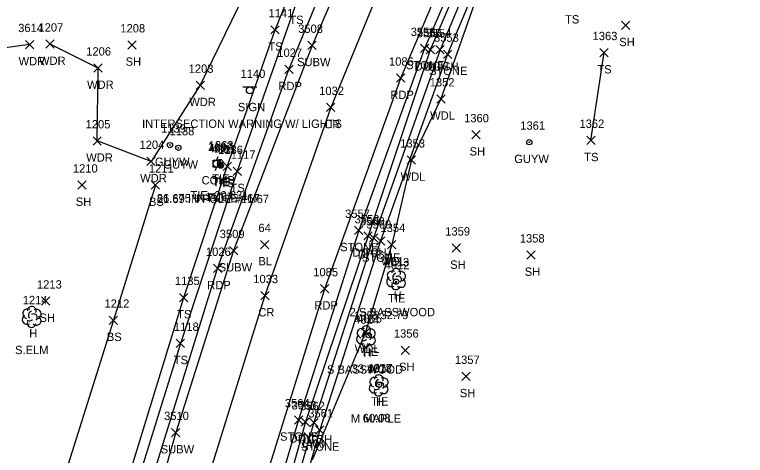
# Model space of a CAD drawing. Extents: x 1634209 to 1639641, y 608564 to 612258.
# Drawn here: x 1639356.8 to 1639532.2, y 611847.1 to 611953 of the extents above; entities that cross this region are included whole.
import ezdxf

# ---------------------------------------------------------------- set-up
doc = ezdxf.new("R2010")
doc.units = 0
for name, color, linetype in [('C_A', 7, 'Continuous'), ('C_C', 7, 'Continuous'), ('C_I', 7, 'Continuous'), ('C_TIC', 7, 'Continuous'), ('CBP', 7, 'Continuous'), ('D_A', 7, 'Continuous'), ('D_I', 7, 'Continuous'), ('D_TIC', 7, 'Continuous'), ('DD', 7, 'Continuous'), ('L_A', 7, 'Continuous'), ('L_C', 7, 'Continuous'), ('L_I', 7, 'Continuous'), ('L_TIC', 7, 'Continuous'), ('LASF', 7, 'Continuous'), ('LAWA', 7, 'Continuous'), ('LELB', 7, 'Continuous'), ('LTD', 7, 'Continuous'), ('P_A', 7, 'Continuous'), ('P_I', 7, 'Continuous'), ('P_TIC', 7, 'Continuous'), ('PET', 7, 'Continuous'), ('PRC', 7, 'Continuous'), ('S_A', 7, 'Continuous'), ('S_C', 7, 'Continuous'), ('S_I', 7, 'Continuous'), ('SSGN', 7, 'Continuous'), ('U_A', 7, 'Continuous'), ('U_C', 7, 'Continuous'), ('U_I', 7, 'Continuous'), ('U_TIC', 7, 'Continuous'), ('UP', 7, 'Continuous'), ('UPGW', 7, 'Continuous'), ('UW', 7, 'Continuous')]:
    doc.layers.add(name, color=color, linetype=linetype)

msp = doc.modelspace()

# ---------------------------------------------------------------- linework, layer by layer
at = {"layer": 'C_TIC'}
for points in [[(1639415.86, 611896.74), (1639417.85, 611898.74)], [(1639417.85, 611896.74), (1639415.86, 611898.74)]]:
    msp.add_lwpolyline(points, dxfattribs=at)
at = {"layer": 'CBP'}
for centre, radius in [((1639406.14, 611917.58), 0.625), ((1639406.14, 611917.58), 0.0833), ((1639406.16, 611916.87), 0.625), ((1639406.3, 611916.69), 0.625), ((1639406.16, 611916.87), 0.0833), ((1639406.3, 611916.69), 0.0833), ((1639448.41, 611888.82), 0.625), ((1639448.41, 611888.82), 0.0833), ((1639441.81, 611875.95), 0.625), ((1639441.81, 611875.95), 0.0833), ((1639444.33, 611864.06), 0.625), ((1639444.33, 611864.06), 0.0833)]:
    msp.add_circle(centre, radius, dxfattribs=at)
at = {"layer": 'D_TIC'}
for points in [[(1639455.59, 611943.52), (1639457.59, 611945.52)], [(1639457.59, 611943.52), (1639455.59, 611945.52)], [(1639457.96, 611943.55), (1639459.96, 611945.55)], [(1639459.96, 611943.55), (1639457.96, 611945.55)], [(1639440.68, 611898.83), (1639442.68, 611900.83)], [(1639442.68, 611898.83), (1639440.68, 611900.83)], [(1639441.97, 611898.33), (1639443.97, 611900.33)], [(1639443.97, 611898.33), (1639441.97, 611900.33)], [(1639425.6, 611854.12), (1639427.6, 611856.12)], [(1639427.6, 611854.12), (1639425.6, 611856.12)], [(1639427.64, 611853.96), (1639429.64, 611855.96)], [(1639429.64, 611853.96), (1639427.64, 611855.96)]]:
    msp.add_lwpolyline(points, dxfattribs=at)
at = {"layer": 'DD'}
for points in [[(1639560.57, 612129.01), (1639556.53, 612119.06), (1639548.81, 612104.26), (1639529.12, 612083.62), (1639507.53, 612047.31), (1639491.18, 612019.02), (1639473.22, 611983.07), (1639456.59, 611944.52), (1639441.68, 611899.83), (1639426.6, 611855.12), (1639414, 611809.64), (1639403.11, 611769.87), (1639390.43, 611727.49), (1639379.87, 611693.81), (1639369.1, 611662.09), (1639367.84, 611659.83)], [(1639561.94, 612128.14), (1639558.11, 612117.59), (1639549.56, 612103.15), (1639530.32, 612082.73), (1639508.94, 612046.64), (1639492.68, 612018.5), (1639474.74, 611982.05), (1639458.96, 611944.55), (1639442.97, 611899.33), (1639428.64, 611854.96), (1639415.08, 611808.28), (1639405.32, 611769.46), (1639392.22, 611726.77), (1639382.52, 611693.71), (1639371.49, 611661), (1639370.19, 611658.57)]]:
    msp.add_lwpolyline(points, dxfattribs=at)
at = {"layer": 'L_TIC'}
for points in [[(1639502.48, 611949.4), (1639504.48, 611951.4)], [(1639504.48, 611949.4), (1639502.48, 611951.4)], [(1639418.32, 611948.32), (1639420.32, 611950.32)], [(1639420.32, 611948.32), (1639418.32, 611950.32)], [(1639359.4, 611944.78), (1639361.4, 611946.78)], [(1639361.4, 611944.78), (1639359.4, 611946.78)], [(1639364.3, 611944.9), (1639366.3, 611946.9)], [(1639366.3, 611944.9), (1639364.3, 611946.9)], [(1639383.96, 611944.69), (1639385.96, 611946.69)], [(1639385.96, 611944.69), (1639383.96, 611946.69)], [(1639454.22, 611943.85), (1639456.22, 611945.85)], [(1639456.22, 611943.85), (1639454.22, 611945.85)], [(1639459.76, 611942.45), (1639461.76, 611944.45)], [(1639461.76, 611942.45), (1639459.76, 611944.45)], [(1639497.31, 611942.84), (1639499.31, 611944.84)], [(1639499.31, 611942.84), (1639497.31, 611944.84)], [(1639375.82, 611939.14), (1639377.82, 611941.14)], [(1639377.82, 611939.14), (1639375.82, 611941.14)], [(1639400.36, 611935), (1639402.36, 611937)], [(1639402.36, 611935), (1639400.36, 611937)], [(1639458.16, 611931.72), (1639460.16, 611933.72)], [(1639460.16, 611931.72), (1639458.16, 611933.72)], [(1639466.55, 611923.11), (1639468.55, 611925.11)], [(1639468.55, 611923.11), (1639466.55, 611925.11)], [(1639375.62, 611921.64), (1639377.62, 611923.64)], [(1639377.62, 611921.64), (1639375.62, 611923.64)], [(1639494.15, 611921.77), (1639496.15, 611923.77)], [(1639496.15, 611921.77), (1639494.15, 611923.77)], [(1639388.58, 611916.71), (1639390.58, 611918.71)], [(1639390.58, 611916.71), (1639388.58, 611918.71)], [(1639451.06, 611917.05), (1639453.06, 611919.05)], [(1639453.06, 611917.05), (1639451.06, 611919.05)], [(1639406.84, 611915.5), (1639408.84, 611917.5)], [(1639408.84, 611915.5), (1639406.84, 611917.5)], [(1639409.24, 611914.34), (1639411.24, 611916.34)], [(1639411.24, 611914.34), (1639409.24, 611916.34)], [(1639372, 611911.03), (1639374, 611913.03)], [(1639374, 611911.03), (1639372, 611913.03)], [(1639389.61, 611911.03), (1639391.61, 611913.03)], [(1639391.61, 611911.03), (1639389.61, 611913.03)], [(1639438.42, 611900.14), (1639440.42, 611902.14)], [(1639440.42, 611900.14), (1639438.42, 611902.14)], [(1639443.67, 611897.59), (1639445.67, 611899.59)], [(1639445.67, 611897.59), (1639443.67, 611899.59)], [(1639446.34, 611896.74), (1639448.34, 611898.74)], [(1639448.34, 611896.74), (1639446.34, 611898.74)], [(1639461.89, 611895.9), (1639463.89, 611897.9)], [(1639463.89, 611895.9), (1639461.89, 611897.9)], [(1639479.79, 611894.22), (1639481.79, 611896.22)], [(1639481.79, 611894.22), (1639479.79, 611896.22)], [(1639363.29, 611883.16), (1639365.29, 611885.16)], [(1639365.29, 611883.16), (1639363.29, 611885.16)], [(1639396.42, 611884.01), (1639398.42, 611886.01)], [(1639398.42, 611884.01), (1639396.42, 611886.01)], [(1639379.51, 611878.56), (1639381.51, 611880.56)], [(1639381.51, 611878.56), (1639379.51, 611880.56)], [(1639440.05, 611875.68), (1639442.05, 611877.68)], [(1639442.05, 611875.68), (1639440.05, 611877.68)], [(1639395.62, 611873), (1639397.62, 611875)], [(1639397.62, 611873), (1639395.62, 611875)], [(1639449.62, 611871.36), (1639451.62, 611873.36)], [(1639451.62, 611871.36), (1639449.62, 611873.36)], [(1639464.2, 611865.06), (1639466.2, 611867.06)], [(1639466.2, 611865.06), (1639464.2, 611867.06)], [(1639423.97, 611854.61), (1639425.97, 611856.61)], [(1639425.97, 611854.61), (1639423.97, 611856.61)], [(1639429.04, 611852.19), (1639431.04, 611854.19)], [(1639431.04, 611852.19), (1639429.04, 611854.19)]]:
    msp.add_lwpolyline(points, dxfattribs=at)
at = {"layer": 'LASF'}
for points in [[(1639558.56, 612130.45), (1639552.86, 612120.18), (1639541.01, 612102.18), (1639527.49, 612085.59), (1639505.85, 612048.28), (1639489.98, 612019.2), (1639472.04, 611983.89), (1639455.22, 611944.85), (1639439.42, 611901.14), (1639424.97, 611855.61), (1639411.65, 611810.44), (1639400.31, 611769.99), (1639387.4, 611727.33), (1639377.22, 611693.8), (1639367.21, 611662.75), (1639359.89, 611644.2)], [(1639564.17, 612127.3), (1639559.55, 612115.01), (1639546.48, 612097.15), (1639532.98, 612081.91), (1639511.96, 612045.66), (1639494.66, 612017.18), (1639476.15, 611980.34), (1639460.76, 611943.45), (1639444.67, 611898.59), (1639430.04, 611853.19), (1639417.13, 611807.26), (1639407.25, 611767.41), (1639395.02, 611725.74), (1639384.78, 611692.04), (1639373.34, 611660.29), (1639366.81, 611640.98)]]:
    msp.add_lwpolyline(points, dxfattribs=at)
at = {"layer": 'LAWA'}
for points in [[(1639621.29, 612162.67), (1639586.37, 612122.18), (1639574.47, 612128.38), (1639569.45, 612130.12), (1639568.95, 612119.64), (1639554.1, 612098.18), (1639539.81, 612087.62), (1639526.58, 612068.13), (1639518.72, 612053.78), (1639510.6, 612040.7), (1639492.01, 612011.11), (1639478.47, 611981.43), (1639467.99, 611958.08), (1639459.16, 611932.72), (1639452.06, 611918.05), (1639447.34, 611897.74), (1639441.05, 611876.68), (1639428.25, 611845.92)], [(1639373.01, 611979.94), (1639388.01, 611971.55), (1639400.87, 611973.02), (1639414.55, 611978.24), (1639413.38, 611960.74), (1639401.36, 611936), (1639389.58, 611917.71), (1639376.62, 611922.64), (1639376.82, 611940.14), (1639365.3, 611945.9)], [(1639360.4, 611945.78), (1639337.86, 611942.69), (1639328.3, 611925.99), (1639325.8, 611899.79), (1639322.13, 611876.77), (1639319.6, 611839.54), (1639313.3, 611808.51), (1639315.96, 611791.14), (1639292.51, 611779.22), (1639297.13, 611749.76), (1639287.19, 611716.77), (1639276.76, 611694.78), (1639243.82, 611692.54), (1639224.95, 611705.38), (1639202.4, 611705.49), (1639183.07, 611705.82), (1639163.18, 611694.66), (1639148.22, 611679.88), (1639133.72, 611654.57), (1639109.62, 611601.39), (1639094.77, 611617.67)]]:
    msp.add_lwpolyline(points, dxfattribs=at)
at = {"layer": 'LELB'}
for points in [[(1639563.38, 612198.7), (1639539.24, 612164.06), (1639514.54, 612127.14), (1639495.77, 612095.8), (1639476.98, 612067.19), (1639457.71, 612031.74), (1639439.5, 611994.46), (1639424.36, 611955.72), (1639410.24, 611915.34), (1639396.62, 611874), (1639380.38, 611821.61)], [(1639383.1, 611838.36), (1639397.42, 611885.01), (1639407.84, 611916.5), (1639419.32, 611949.32), (1639430.83, 611977.53), (1639440.14, 611998.75)], [(1639495.15, 611922.77), (1639498.31, 611943.84)], [(1639390.61, 611912.03), (1639380.51, 611879.56), (1639366.54, 611835.06), (1639350.59, 611799.16), (1639345.37, 611765.77), (1639340.13, 611736.31), (1639333.62, 611715.99), (1639327.33, 611711.48), (1639324.83, 611696.7), (1639315.48, 611694.31), (1639319.67, 611684.85)]]:
    msp.add_lwpolyline(points, dxfattribs=at)
at = {"layer": 'LTD'}
for p, q in [((1639448.36, 611889.51), (1639448.36, 611889.51)), ((1639448.36, 611889.51), (1639448.36, 611889.51)), ((1639360.88, 611880.41), (1639360.88, 611880.41)), ((1639360.88, 611880.41), (1639360.88, 611880.41)), ((1639441.14, 611875.72), (1639441.14, 611875.72)), ((1639441.14, 611875.72), (1639441.14, 611875.72)), ((1639444.18, 611863.96), (1639444.18, 611863.96)), ((1639444.18, 611863.96), (1639444.18, 611863.96))]:
    msp.add_line(p, q, dxfattribs=at)
for centre in [(1639448.41, 611890.94), (1639360.92, 611881.84), (1639441.19, 611877.15), (1639444.23, 611865.39)]:
    msp.add_arc(centre, 1.05, 335.5272, 180.9563, dxfattribs=at)
for centre, major_axis, ratio, start_param, end_param in [((1639447.57, 611890.17), (1.21, -0.51), 0.895232, 1.570796, 4.712389), ((1639449.4, 611890.09), (-1.14, -0.48), 0.949671, 1.570796, 4.712389), ((1639447.28, 611888.8), (0.58, -1.04), 0.959034, 3.141593, 6.283185), ((1639448.15, 611889.97), (-0.208, -0.792), 0.645439, 3.141593, 6.283185), ((1639448.86, 611889.34), (-0.5, 0.667), 0.989748, 3.141593, 6.283185), ((1639449.36, 611888.67), (-1.09, 0.79), 0.841452, 1.570796, 4.712389), ((1639448.36, 611888.01), (0.26, 1.06), 0.942809, 1.570796, 4.712389), ((1639447.9, 611888.76), (-0.625, -0.083), 0.423636, 0, 3.141593), ((1639360.08, 611881.08), (1.21, -0.51), 0.895232, 1.570796, 4.712389), ((1639360.67, 611880.87), (-0.208, -0.792), 0.645439, 3.141593, 6.283185), ((1639361.38, 611880.24), (-0.5, 0.667), 0.989748, 3.141593, 6.283185), ((1639361.92, 611880.99), (-1.14, -0.48), 0.949671, 1.570796, 4.712389), ((1639359.79, 611879.7), (0.58, -1.04), 0.959034, 3.141593, 6.283185), ((1639360.88, 611878.91), (0.26, 1.06), 0.942809, 1.570796, 4.712389), ((1639360.42, 611879.66), (-0.625, -0.083), 0.423636, 0, 3.141593), ((1639361.88, 611879.58), (-1.09, 0.79), 0.841452, 1.570796, 4.712389), ((1639440.35, 611876.39), (1.21, -0.51), 0.895232, 1.570796, 4.712389), ((1639442.18, 611876.3), (-1.14, -0.48), 0.949671, 1.570796, 4.712389), ((1639440.06, 611875.01), (0.58, -1.04), 0.959034, 3.141593, 6.283185), ((1639440.93, 611876.18), (-0.208, -0.792), 0.645439, 3.141593, 6.283185), ((1639441.64, 611875.55), (-0.5, 0.667), 0.989748, 3.141593, 6.283185), ((1639442.14, 611874.89), (-1.09, 0.79), 0.841452, 1.570796, 4.712389), ((1639441.14, 611874.22), (0.26, 1.06), 0.942809, 1.570796, 4.712389), ((1639440.68, 611874.97), (-0.625, -0.083), 0.423636, 0, 3.141593), ((1639443.39, 611864.63), (1.21, -0.51), 0.895232, 1.570796, 4.712389), ((1639443.98, 611864.42), (-0.208, -0.792), 0.645439, 3.141593, 6.283185), ((1639445.23, 611864.54), (-1.14, -0.48), 0.949671, 1.570796, 4.712389), ((1639443.1, 611863.25), (0.58, -1.04), 0.959034, 3.141593, 6.283185), ((1639443.73, 611863.21), (-0.625, -0.083), 0.423636, 0, 3.141593), ((1639444.68, 611863.79), (-0.5, 0.667), 0.989748, 3.141593, 6.283185), ((1639445.18, 611863.13), (-1.09, 0.79), 0.841452, 1.570796, 4.712389), ((1639444.18, 611862.46), (0.26, 1.06), 0.942809, 1.570796, 4.712389)]:
    msp.add_ellipse(centre, major_axis=major_axis, ratio=ratio, start_param=start_param, end_param=end_param, dxfattribs=at)
at = {"layer": 'P_TIC'}
for points in [[(1639421.64, 611938.83), (1639423.64, 611940.83)], [(1639423.64, 611938.83), (1639421.64, 611940.83)], [(1639448.51, 611936.71), (1639450.51, 611938.71)], [(1639450.51, 611936.71), (1639448.51, 611938.71)], [(1639431.7, 611929.67), (1639433.7, 611931.67)], [(1639433.7, 611929.67), (1639431.7, 611931.67)], [(1639404.55, 611891.01), (1639406.55, 611893.01)], [(1639406.55, 611891.01), (1639404.55, 611893.01)], [(1639430.27, 611886.12), (1639432.27, 611888.12)], [(1639432.27, 611886.12), (1639430.27, 611888.12)], [(1639415.88, 611884.46), (1639417.88, 611886.46)], [(1639417.88, 611884.46), (1639415.88, 611886.46)]]:
    msp.add_lwpolyline(points, dxfattribs=at)
at = {"layer": 'PET'}
for points in [[(1639245.26, 611428.04), (1639265.27, 611462.65), (1639285.72, 611496.98), (1639297.96, 611518.63), (1639312.46, 611545.86), (1639331.24, 611585.47), (1639351.91, 611632.95), (1639369.29, 611681.55), (1639385.15, 611732.94), (1639399.72, 611782.78), (1639415.55, 611836.4), (1639431.27, 611887.12), (1639449.51, 611937.71), (1639468.81, 611983.24), (1639484.71, 612016.46), (1639503.95, 612051.42), (1639527.63, 612090.72), (1639556.4, 612135.38), (1639588.32, 612182.52)], [(1639220.96, 611441.47), (1639247.22, 611483.75), (1639268.21, 611519.52), (1639285.57, 611551.38), (1639309.59, 611600.33), (1639328.5, 611645.78), (1639344.08, 611688.66), (1639358.64, 611735.43), (1639372.55, 611782.94), (1639389.96, 611841.92), (1639405.55, 611892.01), (1639422.64, 611939.83), (1639441.75, 611985.91), (1639461.99, 612028.31)]]:
    msp.add_lwpolyline(points, dxfattribs=at)
at = {"layer": 'PRC'}
msp.add_lwpolyline([(1639473.49, 612022.53), (1639453.52, 611981.45), (1639432.7, 611930.67), (1639416.88, 611885.46), (1639401.13, 611834.82), (1639385.48, 611780.16), (1639369.66, 611726.72), (1639353.84, 611677.52), (1639335.57, 611627.61), (1639314.72, 611580.03), (1639292.65, 611536.14), (1639275.3, 611504.78), (1639250.46, 611462.84), (1639222.36, 611418.18)], dxfattribs=at)
at = {"layer": 'SSGN'}
for p, q in [((1639411.62, 611935.62), (1639414.95, 611935.62)), ((1639413.27, 611934.79), (1639413.27, 611934.79))]:
    msp.add_line(p, q, dxfattribs=at)
msp.add_circle((1639413.27, 611934.79), 0.833, dxfattribs=at)
at = {"layer": 'U_TIC'}
for points in [[(1639427.21, 611944.59), (1639429.21, 611946.59)], [(1639429.21, 611944.59), (1639427.21, 611946.59)], [(1639408.39, 611895.28), (1639410.39, 611897.28)], [(1639410.39, 611895.28), (1639408.39, 611897.28)], [(1639394.47, 611851.57), (1639396.47, 611853.57)], [(1639396.47, 611851.57), (1639394.47, 611853.57)]]:
    msp.add_lwpolyline(points, dxfattribs=at)
at = {"layer": 'UP'}
for p, q in [((1639404.47, 611916.34), (1639404.47, 611918.01)), ((1639404.47, 611918.01), (1639406.14, 611918.01)), ((1639405.56, 611918.84), (1639405.31, 611918.01)), ((1639406.14, 611918.01), (1639406.14, 611916.34)), ((1639406.14, 611916.34), (1639404.47, 611916.34)), ((1639405.06, 611915.51), (1639405.31, 611916.34)), ((1639405.31, 611917.18), (1639405.31, 611917.18))]:
    msp.add_line(p, q, dxfattribs=at)
msp.add_circle((1639405.31, 611917.18), 0.833, dxfattribs=at)
at = {"layer": 'UPGW'}
for centre, radius in [((1639480.37, 611922.32), 0.625), ((1639394.1, 611921.62), 0.625), ((1639394.1, 611921.62), 0.0833), ((1639396.12, 611920.98), 0.625), ((1639480.37, 611922.32), 0.0833), ((1639396.12, 611920.98), 0.0833)]:
    msp.add_circle(centre, radius, dxfattribs=at)
at = {"layer": 'UW'}
msp.add_lwpolyline([(1639594.99, 612226.51), (1639569.63, 612190.35), (1639550.67, 612164.48), (1639527.14, 612128.9), (1639506.92, 612097.5), (1639485.03, 612062.24), (1639463.29, 612024.05), (1639448.18, 611991.92), (1639428.21, 611945.59), (1639409.39, 611896.28), (1639395.47, 611852.57), (1639388.14, 611826.68), (1639366.36, 611747.21), (1639350.92, 611692.02), (1639316.38, 611597.42), (1639292.15, 611550.99), (1639279.15, 611528.72), (1639253.95, 611487.01), (1639229.78, 611449.06), (1639200.46, 611402.5), (1639172.27, 611358.67), (1639148.82, 611320.98)], dxfattribs=at)

# ---------------------------------------------------------------- texts
at = {"layer": 'C_A'}
for s, p in [('TIE', (1639404.22, 611912.58)), ('TIE', (1639404.23, 611911.87)), ('TIE', (1639404.38, 611911.69)), ('BL', (1639415.34, 611892.74)), ('TIE', (1639446.49, 611883.82)), ('TIE', (1639439.89, 611870.95)), ('TIE', (1639442.41, 611859.06))]:
    msp.add_text(s, height=2, dxfattribs=at).set_placement(p)
at = {"layer": 'C_C'}
for s, p in [('86.675 IN POLE #67', (1639390.94, 611907.87)), ('21.69 IN POLE #11/67', (1639390.96, 611907.69)), ('TIE=29.831', (1639399.04, 611908.58)), ('32.79', (1639444.65, 611879.82)), ('33.137', (1639437.73, 611866.95)), ('60.08', (1639440.38, 611855.06))]:
    msp.add_text(s, height=2, dxfattribs=at).set_placement(p)
at = {"layer": 'C_I'}
for s, p in [('4016', (1639403.33, 611919.87)), ('1263', (1639403.4, 611920.58)), ('4011', (1639404.09, 611919.69)), ('64', (1639415.34, 611900.74)), ('4012', (1639445.64, 611891.82)), ('4015', (1639439.04, 611878.95)), ('4017', (1639441.56, 611867.06))]:
    msp.add_text(s, height=2, dxfattribs=at).set_placement(p)
at = {"layer": 'D_A'}
for p in [(1639452.82, 611939.52), (1639455.19, 611939.55), (1639437.91, 611894.83), (1639439.21, 611894.33), (1639422.83, 611850.12), (1639424.88, 611849.96)]:
    msp.add_text('DITCH', height=2, dxfattribs=at).set_placement(p)
at = {"layer": 'D_I'}
for s, p in [('3555', (1639453.33, 611947.52)), ('3554', (1639455.7, 611947.55)), ('3558', (1639438.42, 611902.83)), ('3559', (1639439.71, 611902.33)), ('3563', (1639423.29, 611858.12)), ('3562', (1639425.34, 611857.96))]:
    msp.add_text(s, height=2, dxfattribs=at).set_placement(p)
at = {"layer": 'L_A'}
for s, p in [('TS', (1639422.77, 611950.72)), ('TS', (1639488.95, 611950.84)), ('TS', (1639417.73, 611944.32)), ('SH', (1639501.97, 611945.4)), ('WDR', (1639357.76, 611940.78)), ('WDR', (1639362.66, 611940.9)), ('SH', (1639383.45, 611940.69)), ('STONE', (1639450.77, 611939.85)), ('STONE', (1639456.3, 611938.45)), ('TS', (1639496.72, 611938.84)), ('WDR', (1639374.19, 611935.14)), ('WDR', (1639398.73, 611931)), ('WDL', (1639456.57, 611927.72)), ('WDR', (1639373.99, 611917.64)), ('SH', (1639466.04, 611919.11)), ('TS', (1639493.56, 611917.77)), ('WDR', (1639386.94, 611912.71)), ('WDL', (1639449.48, 611913.05)), ('TS', (1639406.25, 611911.5)), ('TS', (1639408.65, 611910.34)), ('SH', (1639371.49, 611907.03)), ('BS', (1639389.05, 611907.03)), ('STONE', (1639434.96, 611896.14)), ('STONE', (1639440.21, 611893.59)), ('WDL', (1639444.75, 611892.74)), ('SH', (1639461.38, 611891.9)), ('SH', (1639479.28, 611890.22)), ('H', (1639447.8, 611884.51)), ('SH', (1639362.78, 611879.16)), ('TS', (1639395.82, 611880.01)), ('H', (1639360.31, 611875.41)), ('BS', (1639378.95, 611874.56)), ('WDL', (1639438.46, 611871.68)), ('H', (1639440.57, 611870.72)), ('TS', (1639395.03, 611869)), ('SH', (1639449.11, 611867.36)), ('SH', (1639463.69, 611861.06)), ('H', (1639443.62, 611858.96)), ('STONE', (1639420.52, 611850.61)), ('STONE', (1639425.59, 611848.19))]:
    msp.add_text(s, height=2, dxfattribs=at).set_placement(p)
at = {"layer": 'L_C'}
for s, p in [('2 S BASSWOOD', (1639437.22, 611880.51)), ('S.ELM', (1639356.91, 611871.41)), ('S BASSWOOD', (1639431.79, 611866.72)), ('M MAPLE', (1639437.54, 611854.96))]:
    msp.add_text(s, height=2, dxfattribs=at).set_placement(p)
at = {"layer": 'L_I'}
for s, p in [('1141', (1639417.76, 611952.32)), ('3614', (1639357.66, 611948.78)), ('1207', (1639362.53, 611948.9)), ('1208', (1639382.19, 611948.69)), ('3556', (1639451.91, 611947.85)), ('3553', (1639457.5, 611946.45)), ('1363', (1639495.57, 611946.84)), ('1206', (1639374, 611943.14)), ('1203', (1639398.59, 611939)), ('1352', (1639456.46, 611935.72)), ('1360', (1639464.72, 611927.11)), ('1205', (1639373.85, 611925.64)), ('1362', (1639492.41, 611925.77)), ('1353', (1639449.37, 611921.05)), ('1204', (1639386.8, 611920.71)), ('1136', (1639405.66, 611919.5)), ('1117', (1639408.68, 611918.34)), ('1210', (1639370.79, 611915.03)), ('1211', (1639389.05, 611915.03)), ('3557', (1639436.16, 611904.14)), ('3560', (1639441.27, 611901.59)), ('1354', (1639444.64, 611900.74)), ('1359', (1639460.19, 611899.9)), ('1358', (1639478.1, 611898.22)), ('4013', (1639445.59, 611892.51)), ('1135', (1639395.29, 611888.01)), ('1213', (1639362.17, 611887.16)), ('1214', (1639358.75, 611883.41)), ('1212', (1639378.38, 611882.56)), ('1355', (1639438.35, 611879.68)), ('4014', (1639438.37, 611878.72)), ('1118', (1639395.06, 611877)), ('1356', (1639447.87, 611875.36)), ('1357', (1639462.51, 611869.06)), ('4018', (1639441.41, 611866.96)), ('3564', (1639421.67, 611858.61)), ('3561', (1639427.3, 611856.19)), ('1400', (1639425.39, 611848.92))]:
    msp.add_text(s, height=2, dxfattribs=at).set_placement(p)
at = {"layer": 'P_A'}
for s, p in [('RDP', (1639420.13, 611934.83)), ('RDP', (1639447, 611932.71)), ('CR', (1639431.13, 611925.67)), ('RDP', (1639403.04, 611887.01)), ('RDP', (1639428.76, 611882.12)), ('CR', (1639415.31, 611880.46))]:
    msp.add_text(s, height=2, dxfattribs=at).set_placement(p)
at = {"layer": 'P_I'}
for s, p in [('1027', (1639419.87, 611942.83)), ('1086', (1639446.69, 611940.71)), ('1032', (1639429.92, 611933.67)), ('1026', (1639402.73, 611895.01)), ('1085', (1639428.5, 611890.12)), ('1033', (1639414.1, 611888.46))]:
    msp.add_text(s, height=2, dxfattribs=at).set_placement(p)
at = {"layer": 'S_A'}
msp.add_text('SIGN', height=2, dxfattribs=at).set_placement((1639410.41, 611929.77))
at = {"layer": 'S_C'}
msp.add_text('INTERSECTION WARNING W/ LIGHTS', height=2, dxfattribs=at).set_placement((1639387.41, 611925.77))
at = {"layer": 'S_I'}
msp.add_text('1140', height=2, dxfattribs=at).set_placement((1639411.04, 611937.77))
at = {"layer": 'U_A'}
for s, p in [('SUBW', (1639424.62, 611940.59)), ('GUYW', (1639390.49, 611916.62)), ('GUYW', (1639392.52, 611915.98)), ('GUYW', (1639476.76, 611917.32)), ('COMB', (1639401.69, 611912.18)), ('SUBW', (1639405.8, 611891.28)), ('SUBW', (1639391.88, 611847.57))]:
    msp.add_text(s, height=2, dxfattribs=at).set_placement(p)
at = {"layer": 'U_C'}
msp.add_text('# 11/67', height=2, dxfattribs=at).set_placement((1639400.36, 611908.18))
at = {"layer": 'U_I'}
for s, p in [('3508', (1639424.88, 611948.59)), ('1139', (1639391.96, 611924.62)), ('1361', (1639478.2, 611925.32)), ('1138', (1639394, 611923.98)), ('1137', (1639403.18, 611920.18)), ('3509', (1639406.05, 611899.28)), ('3510', (1639392.69, 611855.57))]:
    msp.add_text(s, height=2, dxfattribs=at).set_placement(p)

doc.saveas('drawing.dxf')
